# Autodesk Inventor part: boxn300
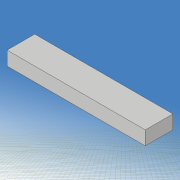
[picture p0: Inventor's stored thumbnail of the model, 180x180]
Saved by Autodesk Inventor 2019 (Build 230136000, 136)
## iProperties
Created: 2021-05
Part Number: boxn300
Material: 一般
Document SubType Name: Modeling
Designer: kikut
Density: 1 g/cm^3
Appearance: 既定
Author: kikut
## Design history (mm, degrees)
sketch "スケッチ1"
  geometry: L1 (-200, -10)-(-400, -10); L2 (-400, -10)-(-400, 10); L3 (-400, 10)-(-200, 10); L4 (-200, 10)-(-200, -10); L5 (-200, -10)-(-400, 10); L6 (-400, -10)-(-200, 10); 2 further points
  constraints: 12 end point, 2 midpoint, 2 parallel, 1 horizontal, 1 perpendicular
  dimensions: "d0" = 20 distance of L1.end L2.end; "d1" = 200 distance of L2.end L3.end; "d2" = 300 distance of point (0, 0) point (-300, 0)
extrude "押し出し1" new body sketch "スケッチ1" stored distance "d3" = 40; taper "d4" = 0 deg
node "ソリッド1"
